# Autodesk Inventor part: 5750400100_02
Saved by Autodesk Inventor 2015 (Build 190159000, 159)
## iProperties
Created: 2020-07
Part Number: 5750400100_02
Checked By: TraceParts S.A.
Material: Generic
Catalog Web Link: www.traceparts.com
Document SubType Name: Modeling
Designer: TraceParts
Density: 1 g/cm^3
Appearance: Default
Company: TraceParts S.A.
Author: TraceParts
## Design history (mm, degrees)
feature "5750400100_02.ipt"
body "Solid1"
